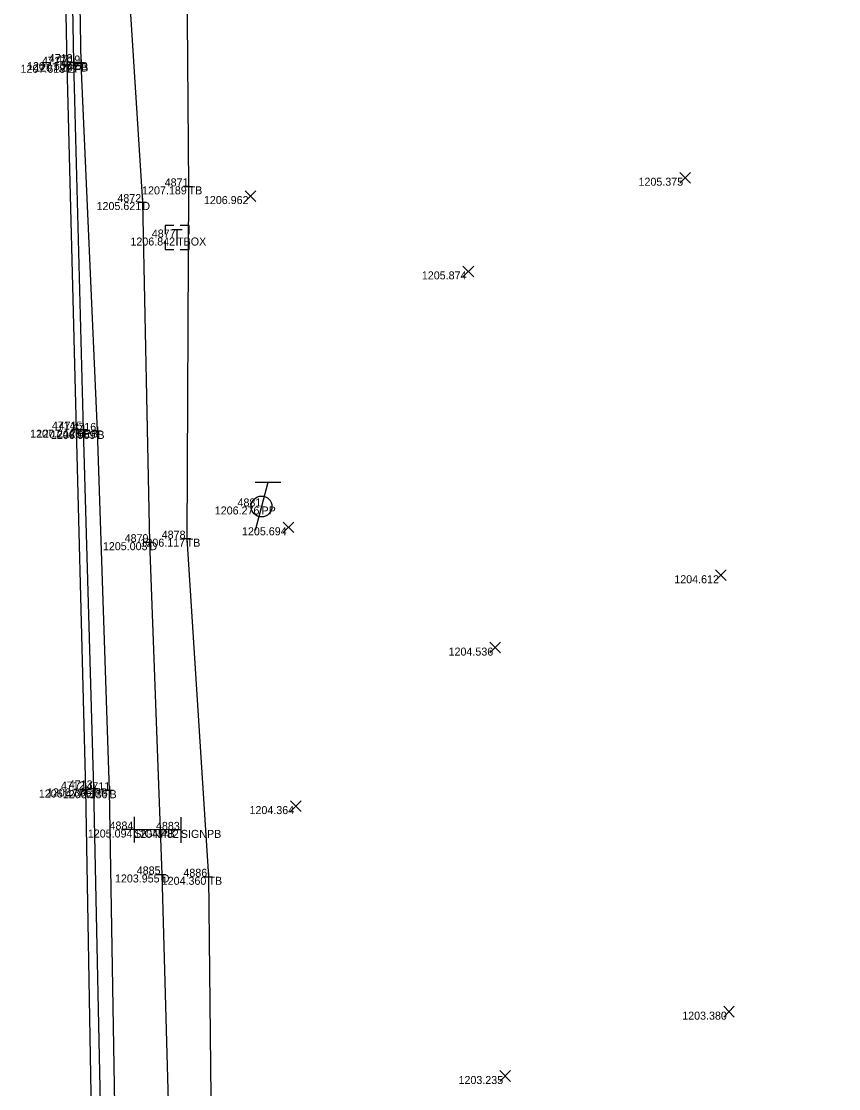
# Model space of a CAD drawing. Extents: x 2044996 to 2050343, y 455232 to 458054.
# Drawn here: x 2047641.8 to 2047743.9, y 456650.7 to 456784 of the extents above; entities that cross this region are included whole.
import ezdxf

# ---------------------------------------------------------------- set-up
doc = ezdxf.new("R2010")
doc.units = 0
for name, color, linetype in [('Default', 7, 'Continuous'), ('DR_X_Ditch', 7, 'Continuous'), ('DT_X_Contour_Minor', 7, 'Continuous'), ('DT_X_Contour_Text', 7, 'Continuous'), ('DT_X_Spot_Elev', 7, 'Continuous'), ('DT_X_TIN_Hull', 7, 'Continuous'), ('DT_X_Triangles', 7, 'Continuous'), ('DT_X_Void', 7, 'Continuous'), ('PV_X_EOP', 7, 'Continuous'), ('PV_X_Shoulder_Aggregate', 7, 'Continuous'), ('SN_X_Public', 7, 'Continuous'), ('SV_X_Break_Lines', 7, 'Continuous'), ('SV_X_Top_of_Bank', 7, 'Continuous'), ('UT_X_Electric_Cells', 7, 'Continuous')]:
    doc.layers.add(name, color=color, linetype=linetype)

msp = doc.modelspace()

# ---------------------------------------------------------------- linework, layer by layer
at = {"layer": 'Default'}
msp.add_lwpolyline([(2047661.75, 456683), (2047655.93, 456683.04)], dxfattribs=at)
at = {"layer": 'DR_X_Ditch'}
msp.add_lwpolyline([(2047944.96, 456861.76), (2047899.25, 456878.16), (2047861.64, 456891.96), (2047815.35, 456909.09), (2047774.86, 456921.86), (2047729.93, 456938.25), (2047691.42, 456950.76), (2047669.22, 456956.37), (2047658.75, 456950.98), (2047651.4, 456909.49), (2047651.98, 456861.4), (2047653.43, 456816.89), (2047656.94, 456761.43), (2047657.83, 456718.94), (2047659.36, 456677.43), (2047660.77, 456628.12), (2047661.37, 456577.1), (2047662.68, 456519.59), (2047665.25, 456466.46), (2047666.16, 456418.54), (2047665.56, 456406.95)], dxfattribs=at)
at = {"layer": 'DT_X_Spot_Elev'}
for p, q in [((2047724.11, 456763.8), (2047725.44, 456765.14)), ((2047724.11, 456765.14), (2047725.44, 456763.8)), ((2047669.8, 456761.52), (2047671.13, 456762.85)), ((2047669.8, 456762.85), (2047671.13, 456761.52)), ((2047697, 456752.1), (2047698.34, 456753.43)), ((2047697, 456753.43), (2047698.34, 456752.1)), ((2047674.53, 456720.13), (2047675.86, 456721.46)), ((2047674.53, 456721.46), (2047675.86, 456720.13)), ((2047728.56, 456714.14), (2047729.9, 456715.48)), ((2047728.56, 456715.48), (2047729.9, 456714.14)), ((2047700.37, 456705.1), (2047701.7, 456706.43)), ((2047700.37, 456706.43), (2047701.7, 456705.1)), ((2047675.47, 456685.3), (2047676.8, 456686.64)), ((2047675.47, 456686.64), (2047676.8, 456685.3)), ((2047729.57, 456659.62), (2047730.9, 456660.96)), ((2047729.57, 456660.96), (2047730.9, 456659.62)), ((2047701.62, 456651.58), (2047702.95, 456652.92)), ((2047701.62, 456652.92), (2047702.95, 456651.58))]:
    msp.add_line(p, q, dxfattribs=at)
at = {"layer": 'DT_X_TIN_Hull'}
for p, q in [((2047660.63, 456758), (2047661.93, 456758)), ((2047661.28, 456756), (2047661.28, 456758)), ((2047661.28, 456757), (2047661.28, 456757))]:
    msp.add_line(p, q, dxfattribs=at)
for points in [[(2047660.88, 456758.5), (2047659.78, 456758.5), (2047659.78, 456757.4)], [(2047662.78, 456757.4), (2047662.78, 456758.5), (2047661.68, 456758.5)], [(2047659.78, 456756.6), (2047659.78, 456755.5), (2047660.88, 456755.5)], [(2047661.68, 456755.5), (2047662.78, 456755.5), (2047662.78, 456756.6)]]:
    msp.add_lwpolyline(points, dxfattribs=at)
at = {"layer": 'DT_X_Void'}
for p, q in [((2047647.56, 456779.08), (2047647.56, 456778.08)), ((2047647.87, 456778.91), (2047648.87, 456778.91)), ((2047648.37, 456779.41), (2047648.37, 456778.41)), ((2047648.37, 456778.91), (2047648.37, 456778.91)), ((2047649.31, 456779.24), (2047649.31, 456778.24)), ((2047647.06, 456778.58), (2047648.06, 456778.58)), ((2047647.56, 456778.58), (2047647.56, 456778.58)), ((2047648.81, 456778.74), (2047649.81, 456778.74)), ((2047649.31, 456778.74), (2047649.31, 456778.74)), ((2047662.22, 456763.39), (2047663.22, 456763.39)), ((2047662.72, 456763.89), (2047662.72, 456762.89)), ((2047662.72, 456763.39), (2047662.72, 456763.39)), ((2047656.94, 456761.93), (2047656.94, 456760.93)), ((2047656.44, 456761.43), (2047657.44, 456761.43)), ((2047656.94, 456761.43), (2047656.94, 456761.43)), ((2047648.23, 456733), (2047649.23, 456733)), ((2047648.73, 456733.5), (2047648.73, 456732.5)), ((2047648.73, 456733), (2047648.73, 456733)), ((2047649.1, 456733), (2047650.1, 456733)), ((2047649.6, 456733.5), (2047649.6, 456732.5)), ((2047649.6, 456733), (2047649.6, 456733)), ((2047650.82, 456732.84), (2047651.82, 456732.84)), ((2047651.32, 456733.34), (2047651.32, 456732.34)), ((2047651.32, 456732.84), (2047651.32, 456732.84)), ((2047657.33, 456718.94), (2047658.33, 456718.94)), ((2047657.83, 456719.44), (2047657.83, 456718.44)), ((2047657.83, 456718.94), (2047657.83, 456718.94)), ((2047661.98, 456719.38), (2047662.98, 456719.38)), ((2047662.48, 456719.88), (2047662.48, 456718.88)), ((2047662.48, 456719.38), (2047662.48, 456719.38)), ((2047649.89, 456688.54), (2047649.89, 456687.54)), ((2047650.86, 456688.68), (2047650.86, 456687.68)), ((2047652.84, 456688.45), (2047652.84, 456687.45)), ((2047649.39, 456688.04), (2047650.39, 456688.04)), ((2047649.89, 456688.04), (2047649.89, 456688.04)), ((2047650.36, 456688.18), (2047651.36, 456688.18)), ((2047650.86, 456688.18), (2047650.86, 456688.18)), ((2047652.34, 456687.95), (2047653.34, 456687.95)), ((2047652.84, 456687.95), (2047652.84, 456687.95)), ((2047659.36, 456677.93), (2047659.36, 456676.93)), ((2047665.2, 456677.64), (2047665.2, 456676.64)), ((2047658.86, 456677.43), (2047659.86, 456677.43)), ((2047659.36, 456677.43), (2047659.36, 456677.43)), ((2047664.7, 456677.14), (2047665.7, 456677.14)), ((2047665.2, 456677.14), (2047665.2, 456677.14))]:
    msp.add_line(p, q, dxfattribs=at)
at = {"layer": 'PV_X_EOP'}
for p, q in [((2047647.56, 456778.58), (2047646.5, 456826.88)), ((2047648.73, 456733), (2047647.56, 456778.58)), ((2047649.89, 456688.04), (2047648.73, 456733)), ((2047650.75, 456639.06), (2047649.89, 456688.04))]:
    msp.add_line(p, q, dxfattribs=at)
at = {"layer": 'PV_X_Shoulder_Aggregate'}
msp.add_lwpolyline([(2047651.94, 456638.93), (2047650.86, 456688.18), (2047649.6, 456733), (2047648.37, 456778.91), (2047647.51, 456826.93), (2047646.86, 456872.4), (2047645.87, 456917.72), (2047645.01, 456938.98), (2047644.95, 456952.82), (2047645.89, 456959.85), (2047646.68, 456960.97), (2047650.24, 456962.76), (2047655.73, 456966.3), (2047657.7, 456966.84), (2047664.7, 456965.75), (2047672.59, 456964.54), (2047677.71, 456963.33), (2047718.66, 456948.27), (2047759.49, 456933.93)], dxfattribs=at)
at = {"layer": 'SN_X_Public'}
for p, q in [((2047655.93, 456684.64), (2047655.93, 456681.44)), ((2047661.75, 456684.6), (2047661.75, 456681.4)), ((2047655.93, 456683.04), (2047654.33, 456683.04)), ((2047661.75, 456683), (2047660.15, 456683))]:
    msp.add_line(p, q, dxfattribs=at)
at = {"layer": 'SV_X_Break_Lines'}
msp.add_lwpolyline([(2047658.43, 456406.25), (2047657.57, 456454.16), (2047657.12, 456499.13), (2047656.02, 456546.18), (2047654.76, 456590.52), (2047653.67, 456638.77), (2047652.84, 456687.95), (2047651.32, 456732.84), (2047649.31, 456778.74), (2047648.48, 456826.81), (2047647.99, 456872.14), (2047647.65, 456917.64), (2047648.11, 456940.22), (2047652.79, 456955.84)], dxfattribs=at)
at = {"layer": 'SV_X_Top_of_Bank'}
msp.add_lwpolyline([(2047942.14, 456857.99), (2047898.01, 456872.36), (2047859.06, 456885.19), (2047815.47, 456901.27), (2047771.85, 456916.42), (2047729.97, 456932.49), (2047688.22, 456947.3), (2047669.99, 456955.17), (2047661.07, 456948.62), (2047656.72, 456911.9), (2047659.76, 456864.17), (2047662.28, 456815.7), (2047662.72, 456763.39), (2047662.48, 456719.38), (2047665.2, 456677.14), (2047665.7, 456629.87), (2047667.28, 456578.15), (2047668.69, 456520.88), (2047669.88, 456466.8), (2047671, 456408.28)], dxfattribs=at)
at = {"layer": 'UT_X_Electric_Cells'}
for p, q in [((2047674.23, 456726.4), (2047671.03, 456726.4)), ((2047672.63, 456726.4), (2047671.03, 456720.4))]:
    msp.add_line(p, q, dxfattribs=at)
msp.add_circle((2047671.83, 456723.4), 1.3, dxfattribs=at)

# ---------------------------------------------------------------- texts
at = {"layer": 'DT_X_Contour_Minor'}
for s, p in [('1207.508', (2047642.53, 456777.91)), ('1207.618', (2047641.72, 456777.58)), ('1207.297', (2047643.43, 456777.74)), ('1205.375', (2047718.93, 456763.47)), ('1207.189', (2047656.91, 456762.39)), ('1206.962', (2047664.63, 456761.18)), ('1205.621', (2047651.22, 456760.43)), ('1206.842', (2047655.45, 456756)), ('1205.874', (2047691.86, 456751.77)), ('1207.244', (2047642.92, 456732)), ('1207.128', (2047643.76, 456732)), ('1206.909', (2047645.51, 456731.84)), ('1206.276', (2047665.99, 456722.4)), ('1205.694', (2047669.39, 456719.8)), ('1205.003', (2047652.01, 456717.94)), ('1206.117', (2047656.7, 456718.38)), ('1204.612', (2047723.4, 456713.81)), ('1204.536', (2047695.2, 456704.77)), ('1206.477', (2047644.01, 456687.04)), ('1206.366', (2047645.02, 456687.18)), ('1206.136', (2047647, 456686.95)), ('1204.364', (2047670.33, 456684.97)), ('1205.094', (2047650.13, 456682.04)), ('1204.482', (2047655.92, 456682)), ('1203.955', (2047653.52, 456676.43)), ('1204.360', (2047659.36, 456676.14)), ('1203.380', (2047724.39, 456659.29)), ('1203.235', (2047696.44, 456651.25))]:
    msp.add_text(s, height=1, dxfattribs=at).set_placement(p)
at = {"layer": 'DT_X_Contour_Text'}
for s, p in [('EB', (2047648.37, 456777.91)), ('EP', (2047647.56, 456777.58)), ('B', (2047649.31, 456777.74)), ('TB', (2047662.72, 456762.39)), ('D', (2047656.94, 456760.43)), ('TBOX', (2047661.28, 456756)), ('EP', (2047648.73, 456732)), ('EB', (2047649.6, 456732)), ('B', (2047651.32, 456731.84)), ('PP', (2047671.83, 456722.4)), ('D', (2047657.83, 456717.94)), ('TB', (2047662.48, 456718.38)), ('EP', (2047649.89, 456687.04)), ('EB', (2047650.86, 456687.18)), ('B', (2047652.84, 456686.95)), ('SIGNPB', (2047655.93, 456682.04)), ('SIGNPB', (2047661.75, 456682)), ('D', (2047659.36, 456676.43)), ('TB', (2047665.2, 456676.14))]:
    msp.add_text(s, height=1, dxfattribs=at).set_placement(p)
at = {"layer": 'DT_X_Triangles'}
for s, p in [('4717', (2047644.4, 456778.58)), ('4718', (2047645.25, 456778.91)), ('4719', (2047646.21, 456778.74)), ('4871', (2047659.73, 456763.39)), ('4872', (2047653.82, 456761.43)), ('4877', (2047658.12, 456757)), ('4714', (2047645.64, 456733)), ('4715', (2047646.47, 456733)), ('4716', (2047648.2, 456732.84)), ('4881', (2047668.83, 456723.4)), ('4878', (2047659.36, 456719.38)), ('4879', (2047654.73, 456718.94)), ('4712', (2047646.77, 456688.04)), ('4713', (2047647.75, 456688.18)), ('4711', (2047649.95, 456687.95)), ('4884', (2047652.84, 456683.04)), ('4883', (2047658.64, 456683)), ('4885', (2047656.24, 456677.43)), ('4886', (2047662.07, 456677.14))]:
    msp.add_text(s, height=1, dxfattribs=at).set_placement(p)

doc.saveas('drawing.dxf')
